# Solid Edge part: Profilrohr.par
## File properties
Username: bmolnar
Dokumentum tartalom típus: 0
Author: bmolnar
Last saved by: bmolnar
Revision: 78
Sűrűség: 0,000 kg/m^3
Pontosság: 0,990
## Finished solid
Body 1: solid body, 63 faces, 178 edges, 112 vertices.
  Faces by surface: cylinder 33, plane 30
  Edges by curve: line 112, circle 66
Bounding box of the edges (mm): 36.000 x 23.400 x 36.000, from (-18, -14.15, -18) to (18, 9.25, 18).
Cylindrical faces by radius (mm): R0.2 x12, R0.5 x12, R3.775 x4, R4.5 x4, R10 x1
Planar faces by outward normal: +x 7, +y 1, +z 7, -x 7, -y 1, -z 7
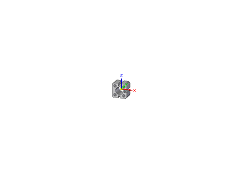
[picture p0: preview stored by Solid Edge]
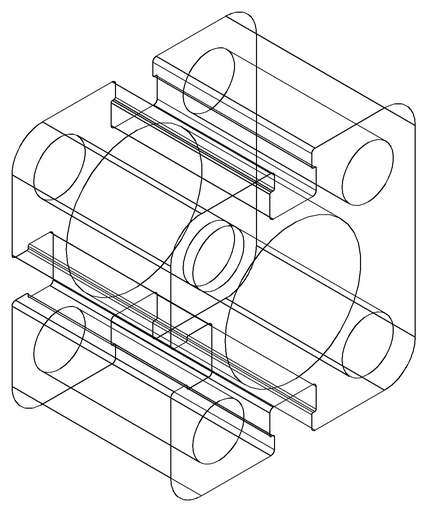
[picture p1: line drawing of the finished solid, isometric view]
